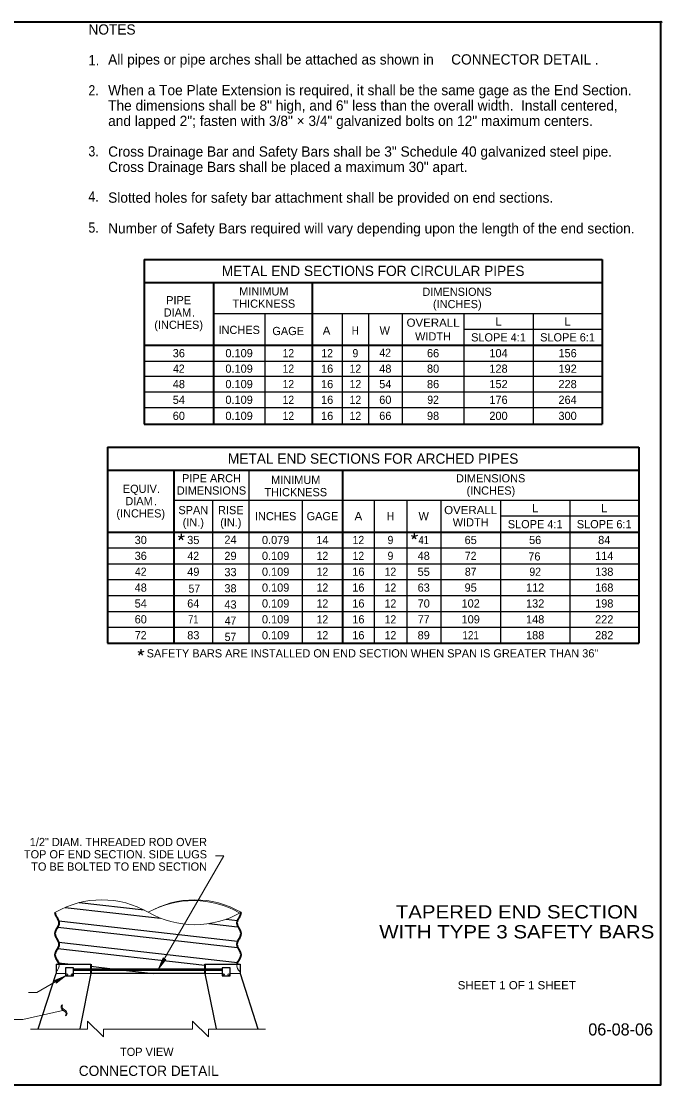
# Model space of a CAD drawing. Extents: x 99860 to 103153, y 99998 to 102077.
# Drawn here: x 101901 to 103153, y 100000 to 102077 of the extents above; entities that cross this region are included whole.
import ezdxf
from ezdxf.enums import TextEntityAlignment as Align

# ---------------------------------------------------------------- set-up
doc = ezdxf.new("R2010")
doc.units = 0
doc.header["$LTSCALE"] = 6.4
doc.header["$PDMODE"] = 32
doc.header["$PDSIZE"] = 3.2
for name, color, linetype, lineweight in [('1', 7, 'Continuous', 13), ('15', 7, 'Continuous', 13), ('18', 7, 'Continuous', 25), ('19', 7, 'Continuous', 25), ('20', 7, 'Continuous', 13), ('6', 7, 'Continuous', 25)]:
    doc.layers.add(name, color=color, linetype=linetype, lineweight=lineweight)
for name, color, linetype in [('11', 7, 'Continuous'), ('60', 7, 'Continuous'), ('62', 7, 'Continuous')]:
    doc.layers.add(name, color=color, linetype=linetype)

msp = doc.modelspace()

# ---------------------------------------------------------------- hatches: boundary and pattern name
at = {"layer": '15'}
for points in [[(102169.273, 100226.058), (102178.103, 100247.321), (102180.16, 100244.914), (102183.273, 100244.336)], [(101987.436, 100212.178), (101966.173, 100203.348), (101968.58, 100201.291), (101969.158, 100198.178)]]:
    msp.add_hatch(color=256, dxfattribs=at).paths.add_polyline_path(points)

# ---------------------------------------------------------------- linework, layer by layer
at = {"layer": '1', "lineweight": 35}
msp.add_lwpolyline([(99862, 99999.5), (103151, 99999.5), (103151, 102075.5), (99862, 102075.5)], close=True, dxfattribs=at)
at = {"layer": '15'}
for p, q in [((102169.273, 100226.058), (102296.791, 100446.925)), ((102280.791, 100446.925), (102296.791, 100446.925)), ((101987.436, 100212.178), (101931.144, 100179.678)), ((101915.144, 100179.678), (101931.144, 100179.678))]:
    msp.add_line(p, q, dxfattribs=at)
for points in [[(102169.273, 100226.058), (102178.103, 100247.321), (102180.16, 100244.914), (102183.273, 100244.336)], [(101987.436, 100212.178), (101966.173, 100203.348), (101968.58, 100201.291), (101969.158, 100198.178)]]:
    msp.add_lwpolyline(points, close=True, dxfattribs=at)
for points in [[(102148.551, 100108.268), (102061.443, 100108.268), (102061.443, 100092.782), (102030.471, 100123.753), (102030.471, 100108.268), (101918.883, 100108.268)], [(102377.91, 100108.268), (102266.631, 100108.268), (102266.631, 100092.782), (102235.659, 100123.753), (102235.659, 100108.268), (102148.551, 100108.268)]]:
    msp.add_lwpolyline(points, dxfattribs=at)
at = {"layer": '18'}
for p, q in [((101969.176, 100235.208), (102037.076, 100235.208)), ((101969.176, 100235.208), (101969.176, 100217.038)), ((102002.856, 100226.058), (102293.726, 100226.058)), ((102002.856, 100223.628), (102293.726, 100223.628)), ((101933.646, 100108.748), (101969.188, 100217.034)), ((102037.076, 100217.038), (102015.186, 100108.538)), ((102259.726, 100217.038), (102281.616, 100108.538))]:
    msp.add_line(p, q, dxfattribs=at)
at = {"layer": '18', "lineweight": 35}
for p, q in [((102037.076, 100235.208), (102037.076, 100226.058)), ((102037.076, 100223.628), (102037.076, 100217.038)), ((102259.726, 100235.208), (102259.726, 100226.058)), ((102259.726, 100223.628), (102259.726, 100217.038))]:
    msp.add_line(p, q, dxfattribs=at)
at = {"layer": '18'}
for points in [[(102002.856, 100227.678), (101987.436, 100227.678), (101987.436, 100212.178), (102002.856, 100212.178)], [(102309.226, 100227.678), (102293.726, 100227.678), (102293.726, 100212.178), (102309.226, 100212.178)]]:
    msp.add_lwpolyline(points, close=True, dxfattribs=at)
msp.add_lwpolyline([(102259.726, 100235.208), (102328.836, 100235.208), (102328.836, 100217.038), (102363.086, 100108.958)], dxfattribs=at)
at = {"layer": '18', "lineweight": 13}
for centre, start, end in [((101990.078, 100214.617), 0, 180), ((101990.078, 100214.617), 180, 0), ((102000.154, 100214.617), 0, 180), ((102000.154, 100214.617), 180, 0), ((102296.414, 100214.617), 0, 180), ((102296.414, 100214.617), 180, 0), ((102306.49, 100214.617), 0, 180), ((102306.49, 100214.617), 180, 0)]:
    msp.add_arc(centre, 1.613, start, end, dxfattribs=at)
at = {"layer": '19', "lineweight": 35}
for p, q in [((102141.07, 101611.936), (102141.07, 101290.206)), ((102141.07, 101611.936), (103036.1, 101611.936)), ((103036.1, 101611.936), (103036.1, 101290.206)), ((102141.07, 101566.936), (103036.1, 101566.936)), ((102276.67, 101566.936), (102276.67, 101290.206)), ((102469.14, 101566.936), (102469.14, 101290.206)), ((102141.07, 101444.186), (103036.1, 101444.186)), ((102141.07, 101290.206), (103036.1, 101290.206)), ((102069.42, 101245.206), (102069.42, 100862.246)), ((102069.42, 101245.206), (103107.75, 101245.206)), ((103107.75, 101245.206), (103107.75, 100862.246)), ((102069.42, 101200.206), (103107.75, 101200.206)), ((102199.37, 101200.206), (102199.37, 100862.246)), ((102528.76, 101200.206), (102528.76, 100862.246)), ((102069.42, 101079.246), (103107.75, 101079.246)), ((102069.42, 100862.246), (103107.75, 100862.246))]:
    msp.add_line(p, q, dxfattribs=at)
at = {"layer": '19'}
for p, q in [((102276.67, 101506.186), (103036.1, 101506.186)), ((102376.6, 101506.186), (102376.6, 101290.206)), ((102528.28, 101506.186), (102528.28, 101290.206)), ((102579.54, 101506.186), (102579.54, 101290.206)), ((102645.3, 101506.186), (102645.3, 101290.206)), ((102766.1, 101506.186), (102766.1, 101290.206)), ((102901.1, 101506.186), (102901.1, 101290.206)), ((103036.1, 101475.186), (102766.1, 101475.186)), ((102141.07, 101413.216), (103036.1, 101413.216)), ((102141.07, 101383.716), (103036.1, 101383.716)), ((102141.07, 101352.956), (103036.1, 101352.956)), ((102141.07, 101322.246), (103036.1, 101322.246)), ((102345.93, 101200.206), (102345.93, 100862.246)), ((102199.37, 101141.236), (103107.75, 101141.236)), ((102274.91, 101141.236), (102274.91, 100862.246)), ((102450.19, 101141.236), (102450.19, 100862.246)), ((102590.71, 101141.236), (102590.71, 100862.246)), ((102654.17, 101141.236), (102654.17, 100862.246)), ((102720.65, 101141.236), (102720.65, 100862.246)), ((102837.75, 101141.236), (102837.75, 100862.246)), ((102972.75, 101141.236), (102972.75, 100862.246)), ((103107.75, 101110.241), (102837.75, 101110.241)), ((102213.478, 101075.698), (102213.478, 101069.406)), ((102668.973, 101077.115), (102668.974, 101070.823)), ((102207.493, 101071.35), (102213.478, 101069.406)), ((102209.78, 101064.315), (102213.478, 101069.406)), ((102219.462, 101071.35), (102213.478, 101069.406)), ((102217.177, 101064.315), (102213.478, 101069.406)), ((102662.989, 101072.767), (102668.974, 101070.823)), ((102665.275, 101065.732), (102668.974, 101070.823)), ((102674.958, 101072.768), (102668.974, 101070.823)), ((102672.673, 101065.732), (102668.974, 101070.823)), ((102069.42, 101048.246), (103107.75, 101048.246)), ((102069.42, 101017.246), (103107.75, 101017.246)), ((102069.42, 100986.246), (103107.75, 100986.246)), ((102069.42, 100955.246), (103107.75, 100955.246)), ((102069.42, 100924.246), (103107.75, 100924.246)), ((102069.42, 100893.246), (103107.75, 100893.246)), ((102134.675, 100850.205), (102134.675, 100843.913)), ((102128.691, 100845.857), (102134.675, 100843.913)), ((102130.977, 100838.822), (102134.675, 100843.913)), ((102140.66, 100845.857), (102134.675, 100843.913)), ((102138.374, 100838.822), (102134.675, 100843.913))]:
    msp.add_line(p, q, dxfattribs=at)
at = {"layer": '20'}
for p, q in [((101984.596, 100145.048), (101904.256, 100126.648)), ((101981.664, 100155.892), (101979.834, 100154.835)), ((101878.756, 100126.648), (101904.256, 100126.648)), ((101987.566, 100134.199), (101989.397, 100135.256))]:
    msp.add_line(p, q, dxfattribs=at)
for points in [[(101979.833, 100154.835), (101979.068, 100153), (101978.778, 100151.232), (101978.973, 100149.537), (101979.649, 100147.91), (101981.399, 100145.827), (101985.02, 100143.306), (101987.01, 100141.922), (101987.96, 100140.76), (101988.439, 100139.421)], [(101989.396, 100135.256), (101990.141, 100137.269), (101990.413, 100139.027), (101990.235, 100140.634), (101989.588, 100142.165), (101988.045, 100144.088), (101984.642, 100146.358), (101982.554, 100147.825), (101981.3, 100149.278), (101980.802, 100150.515), (101980.654, 100151.868), (101980.926, 100153.582), (101981.663, 100155.892)], [(101988.439, 100139.421), (101988.495, 100137.776), (101987.565, 100134.199)]]:
    msp.add_lwpolyline(points, dxfattribs=at)
at = {"layer": '6'}
for p, q in [((102014.223, 100355.218), (102140.83, 100340.918)), ((101986.805, 100345.943), (102172.814, 100324.936)), ((101972.557, 100307.411), (102323.733, 100267.751)), ((101974.357, 100319.58), (102323.723, 100280.12)), ((102267.652, 100314.225), (102323.2, 100307.952)), ((102301.283, 100322.796), (102323.189, 100320.321)), ((101972.439, 100265.656), (102259.726, 100233.211)), ((101974.412, 100277.805), (102323.563, 100238.37)), ((101973.844, 100237.96), (101998.218, 100235.208)), ((102037.076, 100230.819), (102079.23, 100226.058)), ((102100.745, 100223.628), (102159.091, 100217.038)), ((102259.796, 100217.038), (102037.076, 100217.038))]:
    msp.add_line(p, q, dxfattribs=at)
at = {"layer": '6', "lineweight": 13}
for p, q in [((101969.176, 100217.038), (101987.436, 100217.038)), ((102002.856, 100217.038), (102037.076, 100217.038)), ((102259.726, 100217.038), (102293.726, 100217.038)), ((102328.836, 100217.038), (102309.226, 100217.038))]:
    msp.add_line(p, q, dxfattribs=at)
for centre, radius, start, end in [((102058.463, 100179.283), 181.411, 60, 120), ((102239.874, 100179.283), 181.411, 60, 120), ((102237.272, 100179), 180.371, 59.81272, 119.23918), ((102239.874, 100493.497), 181.411, 240, 300), ((101959.775, 100232.376), 15.137, 308.39192, 10.76797), ((102337.544, 100232.568), 15.137, 169.95753, 234.88169)]:
    msp.add_arc(centre, radius, start, end, dxfattribs=at)
at = {"layer": '6', "lineweight": 35}
for centre, start, end in [((101981.876, 100336.401), 180.0381, 223.11161), ((102315.443, 100336.401), 316.88838, 359.96189), ((101959.775, 100315.519), 316.88838, 43.11162), ((102337.544, 100315.519), 136.88838, 223.11161), ((101981.876, 100294.829), 136.88838, 223.11162), ((102315.443, 100294.829), 316.88838, 43.11162), ((101959.775, 100273.947), 316.88838, 43.11162), ((102337.544, 100273.947), 136.88838, 223.11161), ((101981.876, 100253.258), 136.88838, 223.11162), ((102315.443, 100253.258), 316.88838, 43.11162), ((101959.775, 100232.376), 10.76796, 43.11162), ((102337.544, 100232.568), 136.88838, 169.95753)]:
    msp.add_arc(centre, 15.137, start, end, dxfattribs=at)
at = {"layer": '60'}
msp.add_point((103151, 102075.5), dxfattribs=at)

# ---------------------------------------------------------------- texts
at = {"layer": '11'}
msp.add_text('06-08-06', height=23.62, dxfattribs=at).set_placement((103072.262, 100095.777), align=Align.CENTER)
at = {"layer": '19'}
for s, height, p in [('METAL END SECTIONS FOR CIRCULAR PIPES', 20, (102588.588, 101579.436)), ('MINIMUM', 16, (102375.012, 101541.446)), ('DIMENSIONS', 16, (102752.614, 101540.656)), ('PIPE', 16, (102208.508, 101524.206)), ('THICKNESS', 16, (102375.011, 101517.446)), ('(INCHES)', 16, (102753.077, 101516.656)), ('DIAM', 16, (102206.1, 101500.206)), ('(INCHES)', 16, (102208.51, 101476.206)), ('.', 16, (102237.412, 101500.206)), ('INCHES', 16, (102326.825, 101466.161)), ('GAGE', 16, (102422.53, 101464.011)), ('W', 16, (102611.362, 101464.871)), ('WIDTH', 16, (102705.581, 101453.521)), ('SLOPE 4:1', 16, (102833.603, 101451.631)), ('SLOPE 6:1', 16, (102968.502, 101451.631)), ('36', 16, (102208.873, 101420.701)), ('0.109', 16, (102326.636, 101420.701)), ('66', 16, (102705.702, 101420.701)), ('104', 16, (102833.603, 101420.701)), ('156', 16, (102968.603, 101420.701)), ('0.109', 16, (102326.636, 101390.466)), ('16', 16, (102498.712, 101390.466)), ('48', 16, (102612.422, 101390.466)), ('80', 16, (102705.702, 101390.466)), ('128', 16, (102833.603, 101390.466)), ('192', 16, (102968.603, 101390.466)), ('48', 16, (102208.872, 101360.336)), ('0.109', 16, (102326.636, 101360.336)), ('16', 16, (102498.712, 101360.336)), ('54', 16, (102612.422, 101360.336)), ('86', 16, (102705.702, 101360.336)), ('152', 16, (102833.603, 101360.336)), ('228', 16, (102968.603, 101360.336)), ('54', 16, (102208.872, 101329.601)), ('0.109', 16, (102326.636, 101329.601)), ('16', 16, (102498.712, 101329.601)), ('60', 16, (102612.423, 101329.601)), ('176', 16, (102833.603, 101329.601)), ('264', 16, (102968.603, 101329.601)), ('60', 16, (102208.873, 101298.226)), ('0.109', 16, (102326.636, 101298.226)), ('16', 16, (102498.712, 101298.226)), ('66', 16, (102612.423, 101298.226)), ('98', 16, (102705.702, 101298.226)), ('200', 16, (102833.603, 101298.226)), ('300', 16, (102968.603, 101298.226)), ('METAL END SECTIONS FOR ARCHED PIPES', 20, (102588.587, 101212.706)), ('PIPE ARCH', 16, (102272.651, 101176.416)), ('MINIMUM', 16, (102437.346, 101173.136)), ('DIMENSIONS', 16, (102818.249, 101176.271)), ('EQUIV', 16, (102132.662, 101155.726)), ('DIMENSIONS', 16, (102272.651, 101152.416)), ('THICKNESS', 16, (102437.345, 101149.136)), ('(INCHES)', 16, (102818.712, 101152.271)), ('DIAM', 16, (102131.081, 101131.726)), ('.', 16, (102169.346, 101155.726)), ('(INCHES)', 16, (102134.395, 101107.726)), ('.', 16, (102163.297, 101131.726)), ('SPAN', 16, (102237.141, 101114.126)), ('RISE', 16, (102310.421, 101114.126)), ('INCHES', 16, (102398.061, 101102.241)), ('GAGE', 16, (102489.475, 101102.241)), ('W', 16, (102687.411, 101102.241)), ('(IN.)', 16, (102237.141, 101090.126)), ('(IN.)', 16, (102310.421, 101090.126)), ('WIDTH', 16, (102779.201, 101090.241)), ('SLOPE 4:1', 16, (102905.252, 101086.686)), ('SLOPE 6:1', 16, (103040.152, 101086.686)), ('30', 16, (102134.397, 101055.746)), ('35', 16, (102237.141, 101055.746)), ('24', 16, (102309.802, 101056.306)), ('0.079', 16, (102398.06, 101055.746)), ('14', 16, (102489.476, 101055.746)), ('65', 16, (102779.201, 101055.746)), ('56', 16, (102905.252, 101055.746)), ('84', 16, (103040.251, 101055.746)), ('36', 16, (102134.397, 101024.746)), ('29', 16, (102309.806, 101024.656)), ('0.109', 16, (102398.06, 101024.746)), ('48', 16, (102687.411, 101024.746)), ('76', 16, (102903.701, 101023.596)), ('114', 16, (103040.251, 101024.746)), ('49', 16, (102237.141, 100993.746)), ('33', 16, (102309.802, 100993.006)), ('0.109', 16, (102398.06, 100993.746)), ('16', 16, (102559.737, 100993.746)), ('55', 16, (102687.411, 100993.746)), ('138', 16, (103040.251, 100993.746)), ('48', 16, (102134.396, 100962.746)), ('38', 16, (102309.802, 100961.356)), ('0.109', 16, (102398.06, 100962.746)), ('16', 16, (102559.737, 100962.746)), ('63', 16, (102687.411, 100962.746)), ('95', 16, (102779.201, 100962.746)), ('112', 16, (102905.252, 100962.746)), ('168', 16, (103040.251, 100962.746)), ('54', 16, (102134.396, 100931.746)), ('64', 16, (102237.141, 100931.746)), ('43', 16, (102309.802, 100929.706)), ('0.109', 16, (102398.06, 100931.746)), ('16', 16, (102559.737, 100931.746)), ('70', 16, (102687.411, 100931.746)), ('102', 16, (102779.201, 100931.746)), ('132', 16, (102905.252, 100931.746)), ('198', 16, (103040.251, 100931.746)), ('60', 16, (102134.397, 100900.746)), ('0.109', 16, (102398.06, 100900.746)), ('16', 16, (102559.737, 100900.746)), ('109', 16, (102779.201, 100900.746)), ('148', 16, (102905.252, 100900.746)), ('222', 16, (103040.251, 100900.746)), ('83', 16, (102237.141, 100869.746)), ('0.109', 16, (102398.06, 100869.746)), ('16', 16, (102559.737, 100869.746)), ('89', 16, (102687.411, 100869.746)), ('188', 16, (102905.252, 100869.746)), ('282', 16, (103040.251, 100869.746))]:
    msp.add_text(s, height=height, dxfattribs=at).set_placement(p, align=Align.CENTER)
for s, width, p in [('OVERALL', 1.05, (102705.702, 101480.271)), ('L', 1.05, (102833.603, 101482.741)), ('L', 1.05, (102968.602, 101482.741)), ('A', 1.05, (102497.566, 101464.731)), ('H', 0.9, (102553.776, 101464.981)), ('12', 0.95, (102422.872, 101420.701)), ('12', 0.95, (102498.712, 101420.701)), ('9', 0.95, (102553.913, 101420.701)), ('42', 0.95, (102612.114, 101421.596)), ('42', 0.95, (102208.872, 101390.466)), ('12', 0.95, (102422.872, 101390.466)), ('12', 0.95, (102553.912, 101390.466)), ('12', 0.95, (102422.872, 101360.336)), ('12', 0.95, (102553.912, 101360.336)), ('12', 0.95, (102422.872, 101329.601)), ('12', 0.95, (102553.912, 101329.601)), ('92', 0.95, (102705.702, 101329.601)), ('12', 0.95, (102422.872, 101298.226)), ('12', 0.95, (102553.912, 101298.226)), ('A', 1.05, (102559.735, 101102.241)), ('H', 0.9, (102622.441, 101102.241)), ('OVERALL', 1.05, (102779.201, 101114.241)), ('L', 1.05, (102905.252, 101117.796)), ('L', 1.05, (103040.252, 101117.796)), ('12', 0.95, (102559.736, 101055.746)), ('9', 0.95, (102622.441, 101055.746)), ('41', 0.85, (102687.412, 101055.746)), ('42', 0.95, (102237.141, 101024.746)), ('12', 0.95, (102489.476, 101024.746)), ('12', 0.95, (102559.736, 101024.746)), ('9', 0.95, (102622.441, 101024.746)), ('72', 0.95, (102779.201, 101024.746)), ('42', 0.95, (102134.396, 100993.746)), ('12', 0.95, (102489.476, 100993.746)), ('12', 0.95, (102622.441, 100993.746)), ('87', 0.95, (102779.201, 100993.746)), ('92', 0.95, (102905.252, 100993.746)), ('57', 0.95, (102239.133, 100960.726)), ('12', 0.95, (102489.476, 100962.746)), ('12', 0.95, (102622.441, 100962.746)), ('12', 0.95, (102489.476, 100931.746)), ('12', 0.95, (102622.441, 100931.746)), ('71', 0.85, (102237.142, 100900.746)), ('47', 0.95, (102309.803, 100898.056)), ('12', 0.95, (102489.476, 100900.746)), ('12', 0.95, (102622.441, 100900.746)), ('77', 0.95, (102687.411, 100900.746)), ('72', 0.95, (102134.396, 100869.746)), ('57', 0.95, (102309.803, 100866.406)), ('12', 0.95, (102489.476, 100869.746)), ('12', 0.95, (102622.441, 100869.746)), ('121', 0.9, (102779.202, 100869.746))]:
    msp.add_text(s, height=16, dxfattribs=dict(at, width=width)).set_placement(p, align=Align.CENTER)
msp.add_text('SAFETY BARS ARE INSTALLED ON END SECTION WHEN SPAN IS GREATER THAN 36"', height=16, dxfattribs=at).set_placement((102145.984, 100834.27))
at = {"layer": '20'}
for s, p in [('NOTES', (102032.162, 102051.103)), ('All pipes or pipe arches shall be attached as shown in ', (102070.725, 101992.579)), ('CONNECTOR DETAIL', (102741.113, 101992.579)), ('.', (103021.829, 101992.579)), ('When a Toe Plate Extension is required, it shall be the same gage as the End Section.', (102070.725, 101932.579)), ('The dimensions shall be 8" high, and 6" less than the overall width.  Install centered,', (102070.725, 101902.579)), ('and lapped 2"; fasten with 3/8" × 3/4" galvanized bolts on 12" maximum centers.', (102070.725, 101872.579)), ('Cross Drainage Bar and Safety Bars shall be 3" Schedule 40 galvanized steel pipe.', (102070.725, 101812.579)), ('Cross Drainage Bars shall be placed a maximum 30" apart.', (102070.725, 101782.579)), ('Slotted holes for safety bar attachment shall be provided on end sections.', (102070.725, 101722.579)), ('Number of Safety Bars required will vary depending upon the length of the end section. ', (102070.725, 101662.579))]:
    msp.add_text(s, height=20, dxfattribs=at).set_placement(p)
for s, width, p in [('1.', 0.95, (102032.162, 101991.103)), ('2.', 0.9, (102032.162, 101932.23)), ('3.', 0.9, (102032.162, 101813.07)), ('4.', 0.9, (102032.162, 101724.979)), ('5.', 0.9, (102032.162, 101664.086))]:
    msp.add_text(s, height=20, dxfattribs=dict(at, width=width)).set_placement(p)
for s, p in [('1/2" DIAM. THREADED ROD OVER', (102263.939, 100465.697)), ('TOP OF END SECTION. SIDE LUGS', (102263.939, 100441.697)), ('TO BE BOLTED TO END SECTION', (102263.939, 100417.697))]:
    msp.add_text(s, height=16, dxfattribs=at).set_placement(p, align=Align.RIGHT)
for s, height, p in [('TOP VIEW', 16, (102146.249, 100055.799)), ('CONNECTOR DETAIL', 20, (102150.021, 100016.69))]:
    msp.add_text(s, height=height, dxfattribs=at).set_placement(p, align=Align.CENTER)
at = {"layer": '62'}
for s, height, width, p in [('TAPERED END SECTION', 26, 1.15, (102869.354, 100324.3)), ('WITH TYPE 3 SAFETY BARS', 26, 1.15, (102869.354, 100285.3)), ('SHEET 1 OF 1 SHEET', 16, 1.05, (102869.354, 100185.938))]:
    msp.add_text(s, height=height, dxfattribs=dict(at, width=width)).set_placement(p, align=Align.CENTER)

doc.saveas('drawing.dxf')
